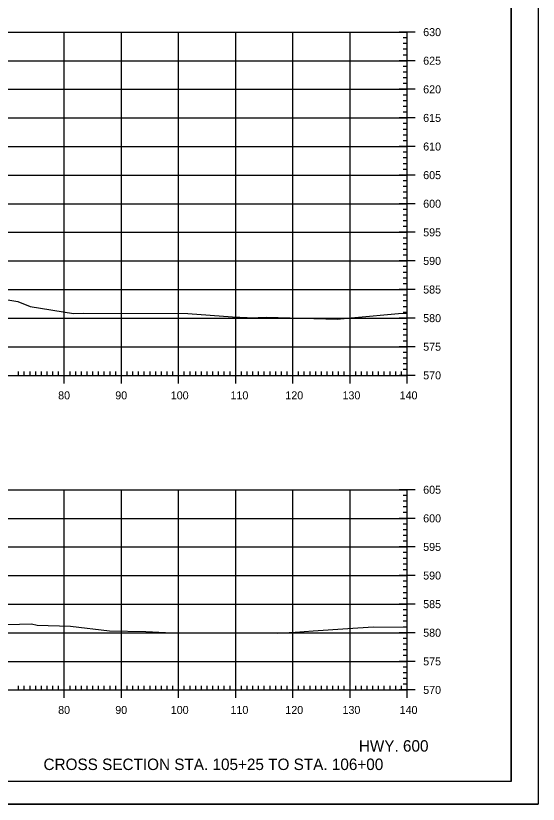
# Model space of a CAD drawing. Extents: x 961436 to 1372525, y 380079 to 2027791.
# Drawn here: x 1370705.3 to 1370796.7, y 380535.8 to 380673.6 of the extents above; entities that cross this region are included whole.
import ezdxf

# ---------------------------------------------------------------- set-up
doc = ezdxf.new("R2010")
doc.units = 0
for name, color, linetype in [('R_Axis', 7, 'Continuous'), ('R_Axis Annot', 7, 'Continuous'), ('R_Draft', 7, 'Continuous'), ('R_Exist Surface', 7, 'Continuous'), ('R_Grid', 7, 'Continuous'), ('R_No Plot', 7, 'Continuous')]:
    doc.layers.add(name, color=color, linetype=linetype)

msp = doc.modelspace()

# ---------------------------------------------------------------- linework, layer by layer
at = {"layer": 'R_Axis'}
for p, q in [((1370775.21, 380670.73), (1370772.41, 380670.73)), ((1370773.81, 380610.73), (1370773.81, 380670.73)), ((1370773.81, 380669.73), (1370773.11, 380669.73)), ((1370773.81, 380668.73), (1370773.11, 380668.73)), ((1370773.81, 380667.73), (1370773.11, 380667.73)), ((1370773.81, 380666.73), (1370773.11, 380666.73)), ((1370775.21, 380665.73), (1370772.41, 380665.73)), ((1370773.81, 380664.73), (1370773.11, 380664.73)), ((1370773.81, 380663.73), (1370773.11, 380663.73)), ((1370773.81, 380662.73), (1370773.11, 380662.73)), ((1370773.81, 380661.73), (1370773.11, 380661.73)), ((1370775.21, 380660.73), (1370772.41, 380660.73)), ((1370773.81, 380659.73), (1370773.11, 380659.73)), ((1370773.81, 380658.73), (1370773.11, 380658.73)), ((1370773.81, 380657.73), (1370773.11, 380657.73)), ((1370773.81, 380656.73), (1370773.11, 380656.73)), ((1370775.21, 380655.73), (1370772.41, 380655.73)), ((1370773.81, 380654.73), (1370773.11, 380654.73)), ((1370773.81, 380653.73), (1370773.11, 380653.73)), ((1370773.81, 380652.73), (1370773.11, 380652.73)), ((1370773.81, 380651.73), (1370773.11, 380651.73)), ((1370775.21, 380650.73), (1370772.41, 380650.73)), ((1370773.81, 380649.73), (1370773.11, 380649.73)), ((1370773.81, 380648.73), (1370773.11, 380648.73)), ((1370773.81, 380647.73), (1370773.11, 380647.73)), ((1370775.21, 380645.73), (1370772.41, 380645.73)), ((1370773.81, 380646.73), (1370773.11, 380646.73)), ((1370773.81, 380644.73), (1370773.11, 380644.73)), ((1370773.81, 380643.73), (1370773.11, 380643.73)), ((1370773.81, 380642.73), (1370773.11, 380642.73)), ((1370773.81, 380641.73), (1370773.11, 380641.73)), ((1370775.21, 380640.73), (1370772.41, 380640.73)), ((1370773.81, 380639.73), (1370773.11, 380639.73)), ((1370773.81, 380638.73), (1370773.11, 380638.73)), ((1370773.81, 380637.73), (1370773.11, 380637.73)), ((1370773.81, 380636.73), (1370773.11, 380636.73)), ((1370775.21, 380635.73), (1370772.41, 380635.73)), ((1370773.81, 380634.73), (1370773.11, 380634.73)), ((1370773.81, 380633.73), (1370773.11, 380633.73)), ((1370773.81, 380632.73), (1370773.11, 380632.73)), ((1370775.21, 380630.73), (1370772.41, 380630.73)), ((1370773.81, 380631.73), (1370773.11, 380631.73)), ((1370773.81, 380629.73), (1370773.11, 380629.73)), ((1370773.81, 380628.73), (1370773.11, 380628.73)), ((1370773.81, 380627.73), (1370773.11, 380627.73)), ((1370773.81, 380626.73), (1370773.11, 380626.73)), ((1370775.21, 380625.73), (1370772.41, 380625.73)), ((1370773.81, 380624.73), (1370773.11, 380624.73)), ((1370773.81, 380623.73), (1370773.11, 380623.73)), ((1370773.81, 380622.73), (1370773.11, 380622.73)), ((1370773.81, 380621.73), (1370773.11, 380621.73)), ((1370775.21, 380620.73), (1370772.41, 380620.73)), ((1370773.81, 380619.73), (1370773.11, 380619.73)), ((1370773.81, 380618.73), (1370773.11, 380618.73)), ((1370773.81, 380617.73), (1370773.11, 380617.73)), ((1370773.81, 380616.73), (1370773.11, 380616.73)), ((1370775.21, 380615.73), (1370772.41, 380615.73)), ((1370773.81, 380614.73), (1370773.11, 380614.73)), ((1370773.81, 380613.73), (1370773.11, 380613.73)), ((1370773.81, 380612.73), (1370773.11, 380612.73)), ((1370705.81, 380610.73), (1370705.81, 380611.43)), ((1370706.81, 380610.73), (1370706.81, 380611.43)), ((1370707.81, 380610.73), (1370707.81, 380611.43)), ((1370708.81, 380610.73), (1370708.81, 380611.43)), ((1370709.81, 380610.73), (1370709.81, 380611.43)), ((1370710.81, 380610.73), (1370710.81, 380611.43)), ((1370711.81, 380610.73), (1370711.81, 380611.43)), ((1370712.81, 380610.73), (1370712.81, 380611.43)), ((1370713.81, 380609.33), (1370713.81, 380612.13)), ((1370714.81, 380610.73), (1370714.81, 380611.43)), ((1370715.81, 380610.73), (1370715.81, 380611.43)), ((1370716.81, 380610.73), (1370716.81, 380611.43)), ((1370717.81, 380610.73), (1370717.81, 380611.43)), ((1370718.81, 380610.73), (1370718.81, 380611.43)), ((1370719.81, 380610.73), (1370719.81, 380611.43)), ((1370720.81, 380610.73), (1370720.81, 380611.43)), ((1370721.81, 380610.73), (1370721.81, 380611.43)), ((1370722.81, 380610.73), (1370722.81, 380611.43)), ((1370723.81, 380609.33), (1370723.81, 380612.13)), ((1370724.81, 380610.73), (1370724.81, 380611.43)), ((1370725.81, 380610.73), (1370725.81, 380611.43)), ((1370726.81, 380610.73), (1370726.81, 380611.43)), ((1370727.81, 380610.73), (1370727.81, 380611.43)), ((1370728.81, 380610.73), (1370728.81, 380611.43)), ((1370729.81, 380610.73), (1370729.81, 380611.43)), ((1370730.81, 380610.73), (1370730.81, 380611.43)), ((1370731.81, 380610.73), (1370731.81, 380611.43)), ((1370732.81, 380610.73), (1370732.81, 380611.43)), ((1370733.81, 380609.33), (1370733.81, 380612.13)), ((1370734.81, 380610.73), (1370734.81, 380611.43)), ((1370735.81, 380610.73), (1370735.81, 380611.43)), ((1370736.81, 380610.73), (1370736.81, 380611.43)), ((1370737.81, 380610.73), (1370737.81, 380611.43)), ((1370738.81, 380610.73), (1370738.81, 380611.43)), ((1370739.81, 380610.73), (1370739.81, 380611.43)), ((1370740.81, 380610.73), (1370740.81, 380611.43)), ((1370741.81, 380610.73), (1370741.81, 380611.43)), ((1370742.81, 380610.73), (1370742.81, 380611.43)), ((1370743.81, 380609.33), (1370743.81, 380612.13)), ((1370744.81, 380610.73), (1370744.81, 380611.43)), ((1370745.81, 380610.73), (1370745.81, 380611.43)), ((1370746.81, 380610.73), (1370746.81, 380611.43)), ((1370747.81, 380610.73), (1370747.81, 380611.43)), ((1370748.81, 380610.73), (1370748.81, 380611.43)), ((1370749.81, 380610.73), (1370749.81, 380611.43)), ((1370750.81, 380610.73), (1370750.81, 380611.43)), ((1370751.81, 380610.73), (1370751.81, 380611.43)), ((1370752.81, 380610.73), (1370752.81, 380611.43)), ((1370753.81, 380609.33), (1370753.81, 380612.13)), ((1370754.81, 380610.73), (1370754.81, 380611.43)), ((1370755.81, 380610.73), (1370755.81, 380611.43)), ((1370756.81, 380610.73), (1370756.81, 380611.43)), ((1370757.81, 380610.73), (1370757.81, 380611.43)), ((1370758.81, 380610.73), (1370758.81, 380611.43)), ((1370759.81, 380610.73), (1370759.81, 380611.43)), ((1370760.81, 380610.73), (1370760.81, 380611.43)), ((1370761.81, 380610.73), (1370761.81, 380611.43)), ((1370762.81, 380610.73), (1370762.81, 380611.43)), ((1370763.81, 380609.33), (1370763.81, 380612.13)), ((1370764.81, 380610.73), (1370764.81, 380611.43)), ((1370765.81, 380610.73), (1370765.81, 380611.43)), ((1370766.81, 380610.73), (1370766.81, 380611.43)), ((1370767.81, 380610.73), (1370767.81, 380611.43)), ((1370768.81, 380610.73), (1370768.81, 380611.43)), ((1370769.81, 380610.73), (1370769.81, 380611.43)), ((1370770.81, 380610.73), (1370770.81, 380611.43)), ((1370771.81, 380610.73), (1370771.81, 380611.43)), ((1370772.81, 380610.73), (1370772.81, 380611.43)), ((1370773.81, 380611.73), (1370773.11, 380611.73)), ((1370773.81, 380609.33), (1370773.81, 380612.13)), ((1370493.81, 380610.73), (1370773.81, 380610.73)), ((1370775.21, 380610.73), (1370772.41, 380610.73)), ((1370775.21, 380590.73), (1370772.41, 380590.73)), ((1370773.81, 380555.73), (1370773.81, 380590.73)), ((1370773.81, 380589.73), (1370773.11, 380589.73)), ((1370773.81, 380588.73), (1370773.11, 380588.73)), ((1370773.81, 380587.73), (1370773.11, 380587.73)), ((1370773.81, 380586.73), (1370773.11, 380586.73)), ((1370775.21, 380585.73), (1370772.41, 380585.73)), ((1370773.81, 380584.73), (1370773.11, 380584.73)), ((1370773.81, 380583.73), (1370773.11, 380583.73)), ((1370773.81, 380582.73), (1370773.11, 380582.73)), ((1370773.81, 380581.73), (1370773.11, 380581.73)), ((1370775.21, 380580.73), (1370772.41, 380580.73)), ((1370773.81, 380579.73), (1370773.11, 380579.73)), ((1370773.81, 380578.73), (1370773.11, 380578.73)), ((1370773.81, 380577.73), (1370773.11, 380577.73)), ((1370773.81, 380576.73), (1370773.11, 380576.73)), ((1370775.21, 380575.73), (1370772.41, 380575.73)), ((1370773.81, 380574.73), (1370773.11, 380574.73)), ((1370773.81, 380573.73), (1370773.11, 380573.73)), ((1370773.81, 380572.73), (1370773.11, 380572.73)), ((1370773.81, 380571.73), (1370773.11, 380571.73)), ((1370775.21, 380570.73), (1370772.41, 380570.73)), ((1370773.81, 380569.73), (1370773.11, 380569.73)), ((1370773.81, 380568.73), (1370773.11, 380568.73)), ((1370773.81, 380567.73), (1370773.11, 380567.73)), ((1370775.21, 380565.73), (1370772.41, 380565.73)), ((1370773.81, 380566.73), (1370773.11, 380566.73)), ((1370773.81, 380564.73), (1370773.11, 380564.73)), ((1370773.81, 380563.73), (1370773.11, 380563.73)), ((1370773.81, 380562.73), (1370773.11, 380562.73)), ((1370773.81, 380561.73), (1370773.11, 380561.73)), ((1370775.21, 380560.73), (1370772.41, 380560.73)), ((1370773.81, 380559.73), (1370773.11, 380559.73)), ((1370773.81, 380558.73), (1370773.11, 380558.73)), ((1370773.81, 380557.73), (1370773.11, 380557.73)), ((1370705.81, 380555.73), (1370705.81, 380556.43)), ((1370706.81, 380555.73), (1370706.81, 380556.43)), ((1370707.81, 380555.73), (1370707.81, 380556.43)), ((1370708.81, 380555.73), (1370708.81, 380556.43)), ((1370709.81, 380555.73), (1370709.81, 380556.43)), ((1370710.81, 380555.73), (1370710.81, 380556.43)), ((1370711.81, 380555.73), (1370711.81, 380556.43)), ((1370712.81, 380555.73), (1370712.81, 380556.43)), ((1370713.81, 380554.33), (1370713.81, 380557.13)), ((1370714.81, 380555.73), (1370714.81, 380556.43)), ((1370715.81, 380555.73), (1370715.81, 380556.43)), ((1370716.81, 380555.73), (1370716.81, 380556.43)), ((1370717.81, 380555.73), (1370717.81, 380556.43)), ((1370718.81, 380555.73), (1370718.81, 380556.43)), ((1370719.81, 380555.73), (1370719.81, 380556.43)), ((1370720.81, 380555.73), (1370720.81, 380556.43)), ((1370721.81, 380555.73), (1370721.81, 380556.43)), ((1370722.81, 380555.73), (1370722.81, 380556.43)), ((1370723.81, 380554.33), (1370723.81, 380557.13)), ((1370724.81, 380555.73), (1370724.81, 380556.43)), ((1370725.81, 380555.73), (1370725.81, 380556.43)), ((1370726.81, 380555.73), (1370726.81, 380556.43)), ((1370727.81, 380555.73), (1370727.81, 380556.43)), ((1370728.81, 380555.73), (1370728.81, 380556.43)), ((1370729.81, 380555.73), (1370729.81, 380556.43)), ((1370730.81, 380555.73), (1370730.81, 380556.43)), ((1370731.81, 380555.73), (1370731.81, 380556.43)), ((1370732.81, 380555.73), (1370732.81, 380556.43)), ((1370733.81, 380554.33), (1370733.81, 380557.13)), ((1370734.81, 380555.73), (1370734.81, 380556.43)), ((1370735.81, 380555.73), (1370735.81, 380556.43)), ((1370736.81, 380555.73), (1370736.81, 380556.43)), ((1370737.81, 380555.73), (1370737.81, 380556.43)), ((1370738.81, 380555.73), (1370738.81, 380556.43)), ((1370739.81, 380555.73), (1370739.81, 380556.43)), ((1370740.81, 380555.73), (1370740.81, 380556.43)), ((1370741.81, 380555.73), (1370741.81, 380556.43)), ((1370742.81, 380555.73), (1370742.81, 380556.43)), ((1370743.81, 380554.33), (1370743.81, 380557.13)), ((1370744.81, 380555.73), (1370744.81, 380556.43)), ((1370745.81, 380555.73), (1370745.81, 380556.43)), ((1370746.81, 380555.73), (1370746.81, 380556.43)), ((1370747.81, 380555.73), (1370747.81, 380556.43)), ((1370748.81, 380555.73), (1370748.81, 380556.43)), ((1370749.81, 380555.73), (1370749.81, 380556.43)), ((1370750.81, 380555.73), (1370750.81, 380556.43)), ((1370751.81, 380555.73), (1370751.81, 380556.43)), ((1370752.81, 380555.73), (1370752.81, 380556.43)), ((1370753.81, 380554.33), (1370753.81, 380557.13)), ((1370754.81, 380555.73), (1370754.81, 380556.43)), ((1370755.81, 380555.73), (1370755.81, 380556.43)), ((1370756.81, 380555.73), (1370756.81, 380556.43)), ((1370757.81, 380555.73), (1370757.81, 380556.43)), ((1370758.81, 380555.73), (1370758.81, 380556.43)), ((1370759.81, 380555.73), (1370759.81, 380556.43)), ((1370760.81, 380555.73), (1370760.81, 380556.43)), ((1370761.81, 380555.73), (1370761.81, 380556.43)), ((1370762.81, 380555.73), (1370762.81, 380556.43)), ((1370763.81, 380554.33), (1370763.81, 380557.13)), ((1370764.81, 380555.73), (1370764.81, 380556.43)), ((1370765.81, 380555.73), (1370765.81, 380556.43)), ((1370766.81, 380555.73), (1370766.81, 380556.43)), ((1370767.81, 380555.73), (1370767.81, 380556.43)), ((1370768.81, 380555.73), (1370768.81, 380556.43)), ((1370769.81, 380555.73), (1370769.81, 380556.43)), ((1370770.81, 380555.73), (1370770.81, 380556.43)), ((1370771.81, 380555.73), (1370771.81, 380556.43)), ((1370772.81, 380555.73), (1370772.81, 380556.43)), ((1370773.81, 380556.73), (1370773.11, 380556.73)), ((1370773.81, 380554.33), (1370773.81, 380557.13)), ((1370493.81, 380555.73), (1370773.81, 380555.73)), ((1370775.21, 380555.73), (1370772.41, 380555.73))]:
    msp.add_line(p, q, dxfattribs=at)
at = {"layer": 'R_Exist Surface'}
for points in [[(1370697.85, 380624.91), (1370705.69, 380623.64), (1370707.85, 380622.78), (1370715.39, 380621.55), (1370717.22, 380621.59), (1370735.44, 380621.53), (1370743.23, 380620.93), (1370745.82, 380620.87), (1370746.35, 380620.8), (1370749.16, 380620.92), (1370761.69, 380620.57), (1370762.13, 380620.62), (1370764.64, 380620.87), (1370772.28, 380621.55), (1370773.81, 380621.6)], [(1370699.54, 380567.08), (1370708.06, 380567.26), (1370709.04, 380567.07), (1370714.9, 380566.89), (1370721.69, 380566.08), (1370728.05, 380565.94), (1370732.71, 380565.73), (1370739.98, 380565.72), (1370751.1, 380565.63), (1370754.22, 380565.86), (1370757.35, 380566.07), (1370763.41, 380566.49), (1370767.83, 380566.76), (1370773.81, 380566.72)]]:
    msp.add_lwpolyline(points, dxfattribs=at)
at = {"layer": 'R_Grid'}
for p, q in [((1370493.81, 380670.73), (1370773.81, 380670.73)), ((1370713.81, 380610.73), (1370713.81, 380670.73)), ((1370723.81, 380610.73), (1370723.81, 380670.73)), ((1370733.81, 380610.73), (1370733.81, 380670.73)), ((1370743.81, 380610.73), (1370743.81, 380670.73)), ((1370753.81, 380610.73), (1370753.81, 380670.73)), ((1370763.81, 380610.73), (1370763.81, 380670.73)), ((1370773.81, 380610.73), (1370773.81, 380670.73)), ((1370493.81, 380665.73), (1370773.81, 380665.73)), ((1370493.81, 380660.73), (1370773.81, 380660.73)), ((1370493.81, 380655.73), (1370773.81, 380655.73)), ((1370493.81, 380650.73), (1370773.81, 380650.73)), ((1370493.81, 380645.73), (1370773.81, 380645.73)), ((1370493.81, 380640.73), (1370773.81, 380640.73)), ((1370493.81, 380635.73), (1370773.81, 380635.73)), ((1370493.81, 380630.73), (1370773.81, 380630.73)), ((1370493.81, 380625.73), (1370773.81, 380625.73)), ((1370493.81, 380620.73), (1370773.81, 380620.73)), ((1370493.81, 380615.73), (1370773.81, 380615.73)), ((1370493.81, 380610.73), (1370773.81, 380610.73)), ((1370493.81, 380590.73), (1370773.81, 380590.73)), ((1370713.81, 380555.73), (1370713.81, 380590.73)), ((1370723.81, 380555.73), (1370723.81, 380590.73)), ((1370733.81, 380555.73), (1370733.81, 380590.73)), ((1370743.81, 380555.73), (1370743.81, 380590.73)), ((1370753.81, 380555.73), (1370753.81, 380590.73)), ((1370763.81, 380555.73), (1370763.81, 380590.73)), ((1370773.81, 380555.73), (1370773.81, 380590.73)), ((1370493.81, 380585.73), (1370773.81, 380585.73)), ((1370493.81, 380580.73), (1370773.81, 380580.73)), ((1370493.81, 380575.73), (1370773.81, 380575.73)), ((1370493.81, 380570.73), (1370773.81, 380570.73)), ((1370493.81, 380565.73), (1370773.81, 380565.73)), ((1370493.81, 380560.73), (1370773.81, 380560.73)), ((1370493.81, 380555.73), (1370773.81, 380555.73))]:
    msp.add_line(p, q, dxfattribs=at)
at = {"layer": 'R_No Plot'}
for p, q in [((1370791.99, 380539.73), (1370791.99, 380745.19)), ((1370791.99, 380539.73), (1370475.81, 380539.73)), ((1370463.41, 380535.76), (1370796.74, 380535.76))]:
    msp.add_line(p, q, dxfattribs=at)
for points in [[(1370463.4, 380749.09), (1370796.74, 380749.09), (1370796.74, 380535.75), (1370463.4, 380535.75)], [(1370709.73, 380745.19), (1370729.35, 380745.19), (1370729.35, 380735.31), (1370745.46, 380735.31), (1370768.66, 380735.31), (1370768.78, 380707.16), (1370791.99, 380707.16), (1370791.99, 380539.73), (1370475.81, 380539.73), (1370475.81, 380745.19)]]:
    msp.add_lwpolyline(points, close=True, dxfattribs=at)

# ---------------------------------------------------------------- texts
at = {"layer": 'R_Axis Annot'}
for s, p in [('630', (1370776.61, 380670.03)), ('625', (1370776.61, 380665.03)), ('620', (1370776.61, 380660.03)), ('615', (1370776.61, 380655.03)), ('610', (1370776.61, 380650.03)), ('605', (1370776.61, 380645.03)), ('600', (1370776.61, 380640.03)), ('595', (1370776.61, 380635.03)), ('590', (1370776.61, 380630.03)), ('585', (1370776.61, 380625.03)), ('580', (1370776.61, 380620.03)), ('575', (1370776.61, 380615.03)), ('570', (1370776.61, 380610.03)), ('80', (1370712.73, 380606.53)), ('90', (1370722.73, 380606.53)), ('100', (1370732.44, 380606.53)), ('110', (1370742.89, 380606.53)), ('120', (1370752.49, 380606.53)), ('130', (1370762.49, 380606.53)), ('140', (1370772.49, 380606.53)), ('605', (1370776.61, 380590.03)), ('600', (1370776.61, 380585.03)), ('595', (1370776.61, 380580.03)), ('590', (1370776.61, 380575.03)), ('585', (1370776.61, 380570.03)), ('580', (1370776.61, 380565.03)), ('575', (1370776.61, 380560.03)), ('570', (1370776.61, 380555.03)), ('80', (1370712.73, 380551.53)), ('90', (1370722.73, 380551.53)), ('100', (1370732.44, 380551.53)), ('110', (1370742.89, 380551.53)), ('120', (1370752.49, 380551.53)), ('130', (1370762.49, 380551.53)), ('140', (1370772.49, 380551.53))]:
    msp.add_text(s, height=1.4, dxfattribs=at).set_placement(p)
at = {"layer": 'R_Draft'}
for s, p in [('HWY. 600', (1370765.35, 380544.95)), ('CROSS SECTION STA. 105+25 TO STA. 106+00', (1370710.17, 380541.73))]:
    msp.add_text(s, height=2, dxfattribs=at).set_placement(p)

doc.saveas('drawing.dxf')
